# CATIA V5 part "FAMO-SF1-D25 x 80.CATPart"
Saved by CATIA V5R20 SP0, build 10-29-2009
Part number: FAMO-SF1-D25 x 80
Definition: NONE
Nomenclature: FAMO-SF1-D25 x 80
Source: Unknown
Description: FAMO-SF1-D25 x 80
Bounding box of the stored display mesh (mm): x -48 to 32, y -22 to 22, z -22 to 22
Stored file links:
  C:\Users\Utente\Desktop\IO LAVORO\3D X SITO CF\X SITO\FAMO\FAMO-SF1-D25 x 80.CATPart
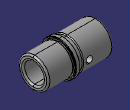
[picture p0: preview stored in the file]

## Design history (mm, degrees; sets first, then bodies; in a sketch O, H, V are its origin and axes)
Body1 "FAMO-SF1-D25 x 80" (main body)
  Solid1: solid without history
